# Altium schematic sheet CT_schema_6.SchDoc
size 226 x 144 mm
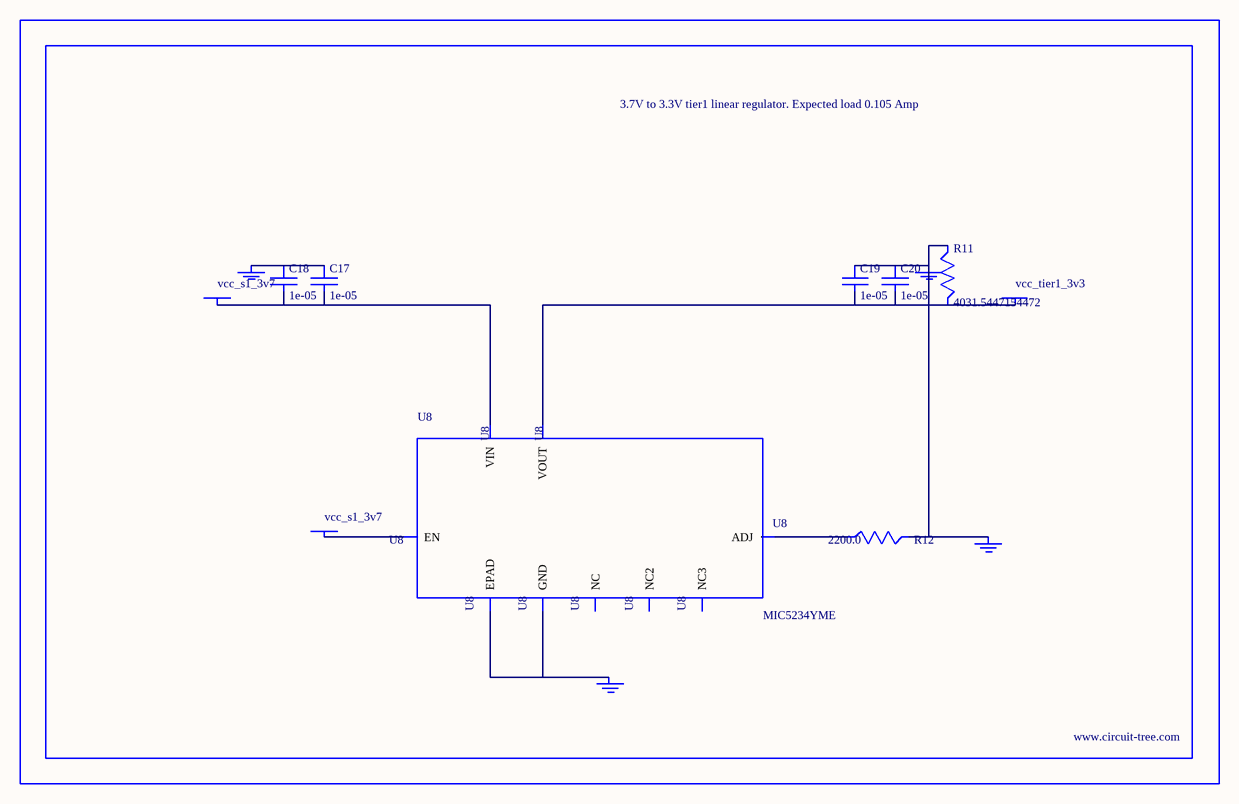
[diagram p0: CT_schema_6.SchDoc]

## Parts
BORDER5  (no value)
C17  1e-05  [C1210]
C18  1e-05  [C1210]
C19  1e-05  [C1210]
C20  1e-05  [C1210]
GND_INSTANCE_5_0  (no value)
GND_INSTANCE_5_1  (no value)
GND_INSTANCE_5_2  (no value)
GND_INSTANCE_5_3  (no value)
POWER_INSTANCE_5_0  vcc_tier1_3v3
POWER_INSTANCE_5_1  vcc_s1_3v7
POWER_INSTANCE_5_2  vcc_s1_3v7
R11  4031.5447154472  [R0603]
R12  2200.0  [R0603]
U8  MIC5234YME  [SOIC-8_EP]

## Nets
NetC17_1: C17.1 C18.1 GND_INSTANCE_5_3.0(GND)
NetC17_2: C17.2 C18.2 POWER_INSTANCE_5_2.0(PWR) U8.8(VIN)
NetC19_1: C19.1 C20.1 GND_INSTANCE_5_0.0(GND) GND_INSTANCE_5_1.0(GND) R11.1 R12.2
NetC19_2: C19.2 C20.2 POWER_INSTANCE_5_0.0(PWR) R11.2 U8.1(VOUT)
NetGND_INSTANCE_5_2_0: GND_INSTANCE_5_2.0(GND) U8.7(GND) U8.EPAD
NetPOWER_INSTANCE_5_1_0: POWER_INSTANCE_5_1.0(PWR) U8.5(EN)
NetR12_1: R12.1 U8.4(ADJ)

Not connected (* = marked no-connect by the designer): U8 2(NC) 3(NC2) 6(NC3)

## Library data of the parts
BORDER5 = BORDER_PAGE5
C17-C20 = C1210C106K5PACTU
GND_INSTANCE_5_0-GND_INSTANCE_5_3 = GND
POWER_INSTANCE_5_0-POWER_INSTANCE_5_2 = PWR
R11 = R11
R12 = RC0603JR-072K2L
